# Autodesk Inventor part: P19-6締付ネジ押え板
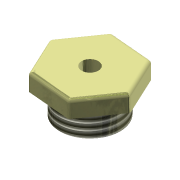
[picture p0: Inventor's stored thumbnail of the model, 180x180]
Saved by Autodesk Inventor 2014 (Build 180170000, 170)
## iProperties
Shininess: 64.0
Length Units: 11269
Angle Units: 11279
Time Units: 11290
Mass Units: 11284
Length Display Precision: 2
Angle Display Precision: 1
Created: 2002-10
Part Number: P19-6締付ネジ押え板
Document SubType Name: ﾓﾃﾞﾘﾝｸﾞ
Designer: 株式会社富士システム
Stock Number: P19-6締付ネジ押え板
Density: 1 g/cm^3
Material: 一般
Appearance: ニッケル
Density: 0.0
Volumn: 0.0
Area: 0.0
PropertySet Name: Model Information
Control State: 0
Master: False
Checked Out: False
Author: 株式会社富士システム
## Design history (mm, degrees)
sketch "ｽｹｯﾁ1"
  geometry: C1 r 18 at (16.993, -14.869)
  constraints: 1 centre point
  dimensions: "d0" = 36 diameter of C1
extrude "押し出し1" new body sketch "ｽｹｯﾁ1" distance "d1" = 15; taper "d2" = 0 deg
sketch "ｽｹｯﾁ2"
  geometry: L1 (11.232, -24.066)-(-15.225, -21.76); L2 (-15.225, -21.76)-(-26.458, 2.305); L3 (-26.458, 2.305)-(-11.232, 24.066); L4 (-11.232, 24.066)-(15.225, 21.76); L5 (15.225, 21.76)-(26.458, -2.305); L6 (26.458, -2.305)-(11.232, -24.066); C1 r 18 at (0, 0) reference; 1 further point
  constraints: 12 end point, 1 coincident, 11 other
  dimensions: "d4" = 23 distance from line of L4 L5.end
extrude "押し出し2" join sketch "ｽｹｯﾁ2" distance "d5" = 10; taper "d6" = 0 deg
feature "ねじ1" dims "d7" = 10, "d8" = 0
sketch "ｽｹｯﾁ3"
  geometry: C1 r 18 at (0, 0) reference; C2 r 5 at (0, 0)
  constraints: 1 centre point, 1 coincident
  dimensions: "d9" = 10 diameter of C2
extrude "押し出し3" cut sketch "ｽｹｯﾁ3" stored distance "d10" = 10; taper "d11" = 0 deg
fillet "ﾌｨﾚｯﾄ1" dims "d12" = 2
node "ソリッド1"
node "ソリッド ボディ"
node "サーフェス ボディ"
